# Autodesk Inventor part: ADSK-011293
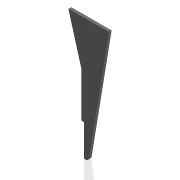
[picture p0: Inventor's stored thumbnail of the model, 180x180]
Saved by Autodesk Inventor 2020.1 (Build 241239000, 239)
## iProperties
Created: 1999-11
Part Number: ADSK-011293
Material: Acier doux
Document SubType Name: Modeling
Designer: sspink
Density: 7.86 g/cm^3
Appearance: Metal-Steel(Polish)
Mass: 526.916 g
Surface Area: 262.462 cm^2
Volume: 67.0377 cm^3
Control State: 0
Checked Out: False
Last Check In By: sspink
Last Check In Date: 1999-12-16
Master: False
Shininess: 0.0
Length Units: 11269
Angle Units: 11279
Time Units: 11290
Mass Units: 11283
Length Display Precision: 3
Angle Display Precision: 2
Compacted: True
Dimensions: 89x270x6 mm
Mass: 0,527 kg
DocNumber: ADSK-011293.ipt
Folder: 01 - Themengebiete\Simplification\01 - Packaging machine\
VDS_Category: 3D Komponenten
Density: 0.0
Volumn: 0.0
Area: 0.0
PropertySet Name: Model Information
Author: sspink
Revision Number: -
Title: plate
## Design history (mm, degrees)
node "Solide1"
  node "Extrusion1" dims "d5" = 6, "d6" = 0
  node "Fillet2" dims "d8" = 12
  node "Fillet3" dims "d9" = 6
sketch "Sketch1"
  geometry: L1 (60, 0)-(14.818, -270); L2 (14.818, -270)-(5.818, -270); L3 (5.818, -270)-(5.818, -199.962); L4 (5.818, -199.962)-(-0.182, -199.962); L5 (-0.182, -199.962)-(0, 0); L6 (-0.092, -101.161)-(-29, 0); L7 (-29, 0)-(60, 0); 1 further point
  constraints: 14 end point, 2 horizontal, 2 point on line, 1 coincident, 1 perpendicular
  dimensions: "d0" = 6 distance of L3.end L4.end; "d1" = 60 distance from line of L5 L1.start; "d10" = 16 deg angle of L5 L6; "d11" = 89 distance of L6.end L1.start; "d12" = 9 distance of L1.end L2.end; "d13" = 270 distance between parallel lines of L7 L2; "d14" = 80.5 deg angle of L1 L7; "d15" = 28.99996 distance from line of L6.end L5
node "Corps solides"
node "Corps surfaciques"
